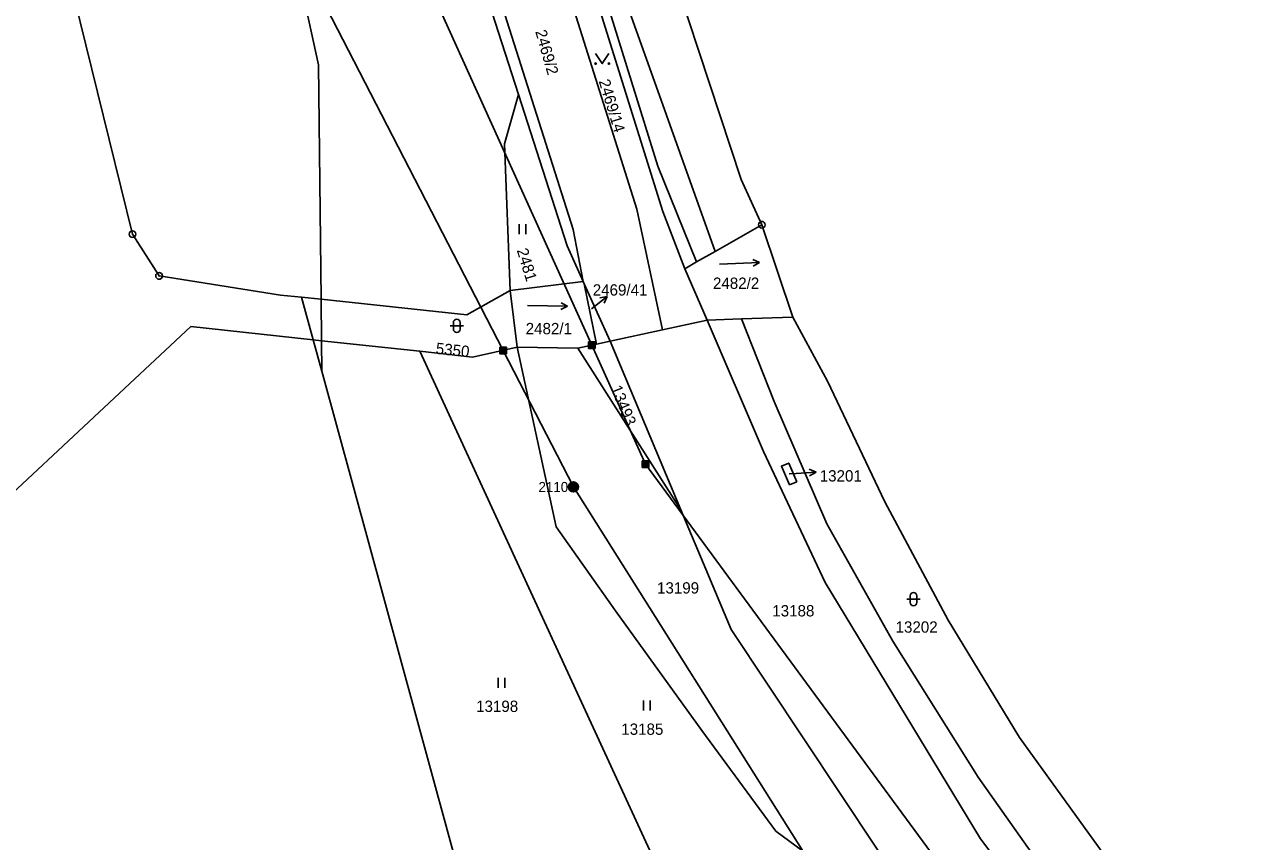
# Model space of a CAD drawing. Extents: x -821458 to -820266, y -1071458 to -1069826.
# Drawn here: x -820683.2 to -820498, y -1070976.8 to -1070854 of the extents above; entities that cross this region are included whole.
import ezdxf

# ---------------------------------------------------------------- set-up
doc = ezdxf.new("R2010")
doc.units = 0
for name, color, linetype in [('Vrstva 1', 7, 'Continuous'), ('Vrstva 2', 7, 'Continuous'), ('Vrstva 3', 7, 'Continuous'), ('Vrstva 4', 7, 'Continuous'), ('Vrstva 6', 7, 'Continuous'), ('Vrstva 7', 7, 'Continuous'), ('Vrstva 8', 7, 'Continuous')]:
    doc.layers.add(name, color=color, linetype=linetype)

msp = doc.modelspace()

# ---------------------------------------------------------------- linework, layer by layer
at = {"layer": 'Vrstva 1'}
for p, q in [((-820572.38, -1070884.09), (-820575.47, -1070877.31)), ((-820587.32, -1070899.89), (-820591.18, -1070881.76)), ((-820579.4, -1070888.1), (-820572.38, -1070884.09)), ((-820567.72, -1070897.98), (-820572.38, -1070884.09)), ((-820580.6, -1070898.43), (-820583.95, -1070890.7)), ((-820610.2, -1070893.97), (-820599.23, -1070892.6)), ((-820599.23, -1070892.6), (-820599.07, -1070892.97)), ((-820599.07, -1070892.97), (-820595.18, -1070901.6)), ((-820599.07, -1070892.97), (-820597.21, -1070902.05)), ((-820644.73, -1070894.66), (-820641.55, -1070894.99)), ((-820641.55, -1070894.99), (-820638.63, -1070895.3)), ((-820639.81, -1070901.39), (-820641.55, -1070894.99)), ((-820610.2, -1070893.97), (-820609.14, -1070902.5)), ((-820580.6, -1070898.43), (-820587.32, -1070899.89)), ((-820575.41, -1070898.25), (-820580.6, -1070898.43)), ((-820567.72, -1070897.98), (-820575.41, -1070898.25)), ((-820658.19, -1070899.4), (-820735.42, -1070971.43)), ((-820639.81, -1070901.39), (-820658.19, -1070899.4)), ((-820587.32, -1070899.89), (-820595.18, -1070901.6)), ((-820638.57, -1070901.52), (-820639.81, -1070901.39)), ((-820623.8, -1070903.11), (-820638.57, -1070901.52)), ((-820600.02, -1070902.66), (-820609.14, -1070902.5)), ((-820597.21, -1070902.05), (-820600.02, -1070902.66)), ((-820584.54, -1070926.95), (-820600.02, -1070902.66)), ((-820595.18, -1070901.6), (-820597.21, -1070902.05)), ((-820595.18, -1070901.6), (-820584.54, -1070926.95)), ((-820584.54, -1070926.95), (-820580.4, -1070936.81)), ((-820561.6, -1070981.6), (-820570.28, -1070975.21))]:
    msp.add_line(p, q, dxfattribs=at)
for points in [[(-820720.44, -1070572.46), (-820743.88, -1070569.76), (-820732.22, -1070617.16), (-820718.37, -1070673.87), (-820707.85, -1070716.96), (-820694.56, -1070770.81), (-820679.24, -1070835.68), (-820666.97, -1070885.51), (-820662.98, -1070891.79), (-820644.73, -1070894.66)], [(-820638.63, -1070895.3), (-820639, -1070860.06), (-820651.05, -1070805.08), (-820667.4, -1070753.6), (-820685.24, -1070696.04), (-820706.9, -1070628.02), (-820713.28, -1070601.74), (-820720.44, -1070572.46)], [(-820575.47, -1070877.31), (-820589.75, -1070833.98), (-820613.15, -1070751.36), (-820619.68, -1070724.73), (-820624.16, -1070691.86), (-820626.98, -1070654.7), (-820626.67, -1070614.41), (-820622.5, -1070571.49)], [(-820630.5, -1070791.8), (-820616.42, -1070841.34), (-820608.96, -1070864.52)], [(-820591.18, -1070881.76), (-820605.01, -1070837.88), (-820617.76, -1070792.61), (-820611.45, -1070801.61)], [(-820627.05, -1070796.31), (-820614.77, -1070840.62), (-820600.74, -1070884.82), (-820599.23, -1070892.6)], [(-820603.74, -1070812.61), (-820594, -1070847.1), (-820579.4, -1070888.1)], [(-820601.24, -1070837.38), (-820587.25, -1070882.1), (-820583.95, -1070890.7)], [(-820608.96, -1070864.52), (-820611.07, -1070871.94), (-820610.2, -1070893.97)], [(-820599.23, -1070892.6), (-820601.65, -1070887.25), (-820608.96, -1070864.52)], [(-820583.95, -1070890.7), (-820582.18, -1070889.69), (-820579.4, -1070888.1)], [(-820638.63, -1070895.3), (-820616.72, -1070897.64), (-820610.2, -1070893.97)], [(-820505.46, -1071018.65), (-820525.24, -1070995.31), (-820539.52, -1070976.39), (-820562.83, -1070937.87), (-820572.14, -1070918.15), (-820580.6, -1070898.43)], [(-820575.41, -1070898.25), (-820570.53, -1070910.66), (-820562.59, -1070929.03), (-820552.69, -1070946.67), (-820539.84, -1070967.11), (-820528.16, -1070983.62), (-820516.84, -1071000.47), (-820503.22, -1071015.12), (-820488.13, -1071031.13), (-820440.56, -1071079.73), (-820404.7, -1071115.79), (-820365.81, -1071154.53), (-820359.33, -1071162.29), (-820347, -1071174.7)], [(-820482, -1071025.25), (-820497.26, -1071009.41), (-820509.99, -1070993.9), (-820521.81, -1070977.53), (-820533.63, -1070961.15), (-820544.37, -1070943.51), (-820553.9, -1070925.73), (-820562.49, -1070907.6), (-820567.72, -1070897.98)], [(-820639.81, -1070901.39), (-820638.53, -1070906.11), (-820612.61, -1071000.86)], [(-820609.14, -1070902.5), (-820615.85, -1070903.97), (-820623.8, -1070903.11)], [(-820570.28, -1070975.21), (-820581.36, -1070960.12), (-820594.37, -1070942.12), (-820603.27, -1070929.48), (-820609.14, -1070902.5)], [(-820623.8, -1070903.11), (-820584.54, -1070988.24), (-820548.09, -1071061.35), (-820571.9, -1071098.21)], [(-820567.1, -1070922.72), (-820568.2, -1070923.17), (-820569.41, -1070920.39), (-820568.32, -1070919.92), (-820567.1, -1070922.72)], [(-820580.4, -1070936.81), (-820577, -1070944.9), (-820544.2, -1070994.2)]]:
    msp.add_lwpolyline(points, dxfattribs=at)
at = {"layer": 'Vrstva 3'}
for p, q in [((-820608.85, -1070885.51), (-820608.85, -1070884.01)), ((-820607.85, -1070885.51), (-820607.85, -1070884.01)), ((-820578.71, -1070890), (-820572.71, -1070889.79)), ((-820572.71, -1070889.79), (-820573.71, -1070889.33)), ((-820572.71, -1070889.79), (-820573.67, -1070890.33)), ((-820607.58, -1070896.25), (-820601.58, -1070896.35)), ((-820601.58, -1070896.35), (-820602.57, -1070896.84)), ((-820601.58, -1070896.35), (-820602.55, -1070895.83)), ((-820618.73, -1070898.8), (-820618.73, -1070899.8)), ((-820617.73, -1070899.8), (-820617.73, -1070898.8)), ((-820619.23, -1070899.3), (-820617.23, -1070899.3)), ((-820550.08, -1070939.86), (-820550.08, -1070940.86)), ((-820549.08, -1070940.86), (-820549.08, -1070939.86)), ((-820550.58, -1070940.36), (-820548.58, -1070940.36)), ((-820611.98, -1070953.67), (-820611.98, -1070952.17)), ((-820610.98, -1070953.67), (-820610.98, -1070952.17)), ((-820590.16, -1070957.11), (-820590.16, -1070955.61)), ((-820589.16, -1070957.11), (-820589.16, -1070955.61))]:
    msp.add_line(p, q, dxfattribs=at)
msp.add_lwpolyline([(-820597.36, -1070858.37), (-820596.36, -1070859.87), (-820595.36, -1070858.37)], dxfattribs=at)
for centre in [(-820597.36, -1070859.87), (-820595.36, -1070859.87)]:
    msp.add_circle(centre, 0.1, dxfattribs=at)
for centre, start, end in [((-820618.23, -1070898.8), 0, 180), ((-820618.23, -1070899.8), 180, 359.9879), ((-820549.58, -1070939.86), 0, 180), ((-820549.58, -1070940.86), 180, 359.9879)]:
    msp.add_arc(centre, 0.5, start, end, dxfattribs=at)
at = {"layer": 'Vrstva 4'}
for p, q in [((-820596.5, -1070847.9), (-820588, -1070875.3)), ((-820588, -1070875.3), (-820582.18, -1070889.69)), ((-820638.63, -1070895.3), (-820638.57, -1070901.52)), ((-820638.53, -1070906.11), (-820638.57, -1070901.52))]:
    msp.add_line(p, q, dxfattribs=at)
at = {"layer": 'Vrstva 6'}
for p, q in [((-820639.4, -1070810.55), (-820597.93, -1070902.2)), ((-820654.22, -1070819.58), (-820611.27, -1070902.97)), ((-820611.77, -1070902.47), (-820610.77, -1070902.47)), ((-820611.77, -1070903.47), (-820611.77, -1070902.47)), ((-820611.77, -1070902.67), (-820610.77, -1070902.67)), ((-820611.77, -1070902.87), (-820610.77, -1070902.87)), ((-820611.57, -1070903.47), (-820611.57, -1070902.47)), ((-820611.37, -1070903.47), (-820611.37, -1070902.47)), ((-820611.17, -1070903.47), (-820611.17, -1070902.47)), ((-820610.97, -1070903.47), (-820610.97, -1070902.47)), ((-820610.77, -1070903.47), (-820610.77, -1070902.47)), ((-820598.43, -1070901.7), (-820597.43, -1070901.7)), ((-820598.43, -1070902.7), (-820598.43, -1070901.7)), ((-820598.43, -1070901.9), (-820597.43, -1070901.9)), ((-820598.43, -1070902.1), (-820597.43, -1070902.1)), ((-820598.43, -1070902.3), (-820597.43, -1070902.3)), ((-820598.43, -1070902.5), (-820597.43, -1070902.5)), ((-820598.43, -1070902.7), (-820597.43, -1070902.7)), ((-820598.23, -1070902.7), (-820598.23, -1070901.7)), ((-820598.03, -1070902.7), (-820598.03, -1070901.7)), ((-820597.93, -1070902.2), (-820589.85, -1070920.06)), ((-820597.83, -1070902.7), (-820597.83, -1070901.7)), ((-820597.63, -1070902.7), (-820597.63, -1070901.7)), ((-820597.43, -1070902.7), (-820597.43, -1070901.7)), ((-820611.77, -1070903.07), (-820610.77, -1070903.07)), ((-820611.77, -1070903.27), (-820610.77, -1070903.27)), ((-820611.77, -1070903.47), (-820610.77, -1070903.47)), ((-820611.27, -1070902.97), (-820600.69, -1070923.5)), ((-820590.35, -1070919.56), (-820589.35, -1070919.56)), ((-820590.35, -1070920.56), (-820590.35, -1070919.56)), ((-820590.35, -1070919.76), (-820589.35, -1070919.76)), ((-820590.35, -1070919.96), (-820589.35, -1070919.96)), ((-820590.35, -1070920.16), (-820589.35, -1070920.16)), ((-820590.35, -1070920.36), (-820589.35, -1070920.36)), ((-820590.35, -1070920.56), (-820589.35, -1070920.56)), ((-820590.15, -1070920.56), (-820590.15, -1070919.56)), ((-820589.95, -1070920.56), (-820589.95, -1070919.56)), ((-820589.85, -1070920.06), (-820514.94, -1071021.94)), ((-820589.75, -1070920.56), (-820589.75, -1070919.56)), ((-820589.55, -1070920.56), (-820589.55, -1070919.56)), ((-820589.35, -1070920.56), (-820589.35, -1070919.56)), ((-820601.19, -1070923), (-820600.19, -1070923)), ((-820601.19, -1070924), (-820601.19, -1070923)), ((-820601.19, -1070923.2), (-820600.19, -1070923.2)), ((-820600.99, -1070924), (-820600.99, -1070923)), ((-820600.79, -1070924), (-820600.79, -1070923)), ((-820600.59, -1070924), (-820600.59, -1070923)), ((-820600.39, -1070924), (-820600.39, -1070923)), ((-820600.19, -1070924), (-820600.19, -1070923)), ((-820601.19, -1070923.4), (-820600.19, -1070923.4)), ((-820601.19, -1070923.6), (-820600.19, -1070923.6)), ((-820601.19, -1070923.8), (-820600.19, -1070923.8)), ((-820601.19, -1070924), (-820600.19, -1070924)), ((-820600.69, -1070923.5), (-820528.19, -1071038.53))]:
    msp.add_line(p, q, dxfattribs=at)
at = {"layer": 'Vrstva 7'}
for p, q in [((-820597.97, -1070896.71), (-820595.6, -1070894.86)), ((-820595.6, -1070894.86), (-820596.7, -1070895.08)), ((-820595.6, -1070894.86), (-820596.09, -1070895.87)), ((-820567.21, -1070921.47), (-820564.22, -1070921.26)), ((-820564.22, -1070921.26), (-820565.25, -1070920.83)), ((-820564.22, -1070921.26), (-820565.18, -1070921.83)), ((-820568.26, -1070921.55), (-820567.21, -1070921.47))]:
    msp.add_line(p, q, dxfattribs=at)
at = {"layer": 'Vrstva 8'}
for centre, radius in [((-820572.38, -1070884.09), 0.5), ((-820572.38, -1070884.09), 0.0303), ((-820666.97, -1070885.51), 0.5), ((-820666.97, -1070885.51), 0.0303), ((-820662.98, -1070891.79), 0.5), ((-820662.98, -1070891.79), 0.0303), ((-820600.69, -1070923.5), 0.75), ((-820600.69, -1070923.5), 0.03)]:
    msp.add_circle(centre, radius, dxfattribs=at)

# ---------------------------------------------------------------- texts
at = {"layer": 'Vrstva 2'}
for s, rotation, p in [('2469/2', 286, (-820606.44, -1070855.05)), ('2469/14', 287, (-820596.9, -1070862.52)), ('2481', 287, (-820609.22, -1070887.92)), ('5350', 354, (-820621.44, -1070903.49)), ('13493', 292, (-820595.12, -1070908.61))]:
    msp.add_text(s, height=1.7, rotation=rotation, dxfattribs=at).set_placement(p)
for s, p in [('2469/41', (-820597.78, -1070894.74)), ('2482/2', (-820579.71, -1070893.73)), ('2482/1', (-820607.86, -1070900.55)), ('13201', (-820563.66, -1070922.68)), ('13199', (-820588.12, -1070939.52)), ('13188', (-820570.79, -1070942.96)), ('13202', (-820552.26, -1070945.4)), ('13198', (-820615.31, -1070957.31)), ('13185', (-820593.49, -1070960.75))]:
    msp.add_text(s, height=1.7, dxfattribs=at).set_placement(p)
at = {"layer": 'Vrstva 8'}
msp.add_text('2110', height=1.5, dxfattribs=at).set_placement((-820605.94, -1070924.25))

doc.saveas('drawing.dxf')
